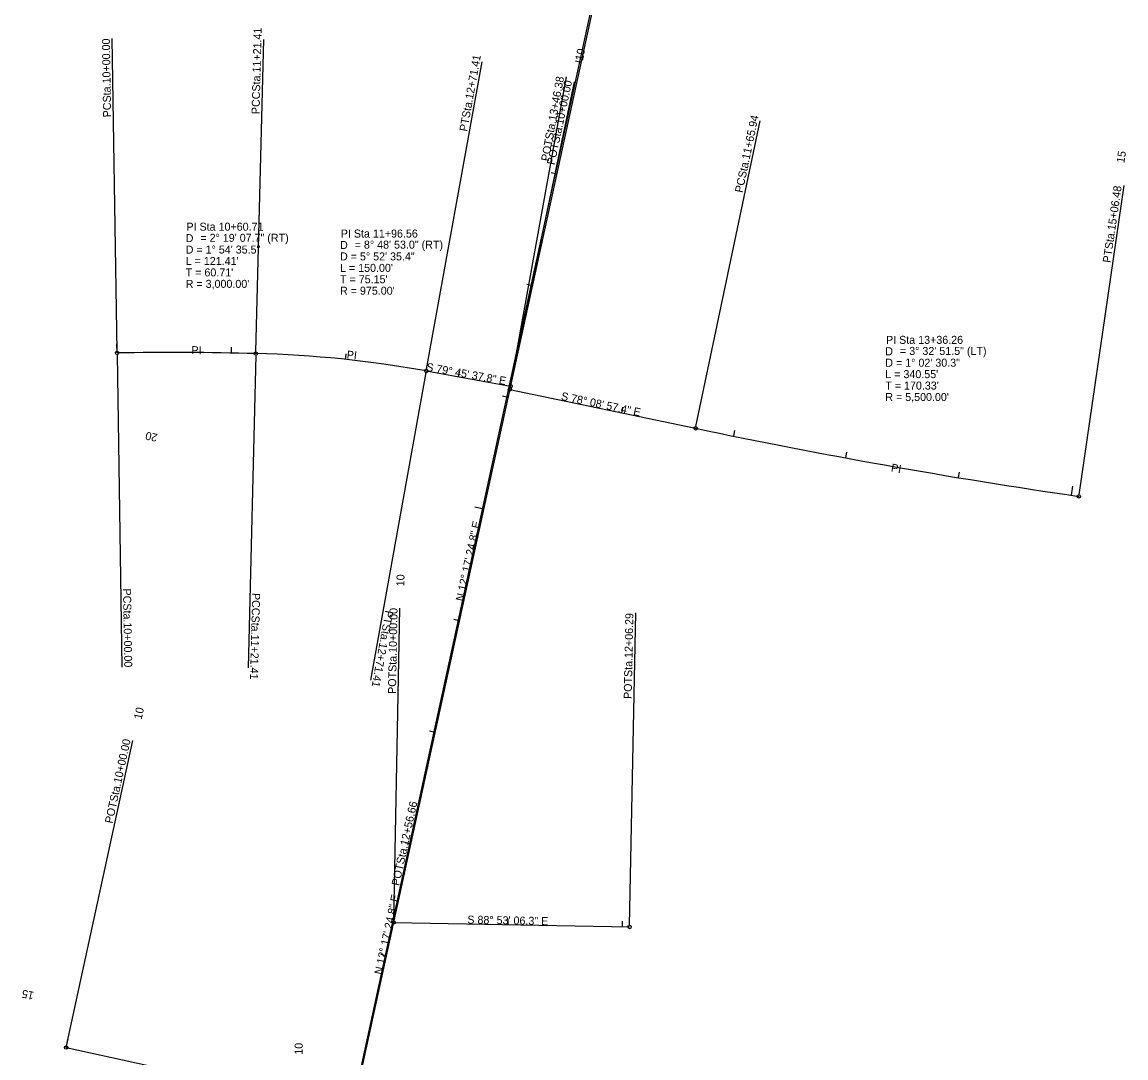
# Model space of a CAD drawing. Extents: x 1615740 to 1617154, y 899624 to 904812.
# Drawn here: x 1615997 to 1616963, y 900122 to 901029 of the extents above; entities that cross this region are included whole.
import ezdxf

# ---------------------------------------------------------------- set-up
doc = ezdxf.new("R2010")
doc.units = 0
for name, color, linetype in [('Default', 7, 'Continuous'), ('Exist Plan Preparation Drainage Flow Arrows', 7, 'Continuous'), ('Exist Plan Preparation Drainage Notes Label', 7, 'Continuous'), ('Exist Structure Minor Pipes CMP 15 Inch Text', 7, 'Continuous'), ('Exist Structure Minor Pipes CMP 24 Inch Text', 7, 'Continuous'), ('Exist Structure Minor Pipes RCP 12 Inch Text', 7, 'Continuous'), ('Exist Structure Minor Pipes RCP 24 Inch Text', 7, 'Continuous'), ('Prop Plan Preparation Sag', 7, 'Continuous'), ('Scratch_Level_7', 7, 'Continuous')]:
    doc.layers.add(name, color=color, linetype=linetype)

msp = doc.modelspace()

# ---------------------------------------------------------------- linework, layer by layer
at = {"layer": 'Default'}
for p, q in [((1616230.15, 899820.83), (1616641.95, 901715.87)), ((1616187.68, 899625.39), (1616607.18, 901555.86)), ((1616187.68, 899625.39), (1616542.07, 901256.25)), ((1616187.68, 899625.39), (1616542.07, 901256.25)), ((1616187.68, 899625.39), (1616542.07, 901256.25)), ((1616187.68, 899625.39), (1616542.07, 901256.25))]:
    msp.add_line(p, q, dxfattribs=at)
at = {"layer": 'Exist Plan Preparation Drainage Flow Arrows'}
for p, q in [((1616080.31, 900739.07), (1616080.19, 900747.07)), ((1616080.31, 900739.07), (1616080.19, 900747.07)), ((1616080.31, 900739.07), (1616080.19, 900747.07)), ((1616080.31, 900739.07), (1616080.19, 900747.07)), ((1616423.96, 900707.19), (1616425.6, 900715.02)), ((1616423.96, 900707.19), (1616425.6, 900715.02)), ((1616423.96, 900707.19), (1616425.6, 900715.02)), ((1616423.96, 900707.19), (1616425.6, 900715.02)), ((1616915.19, 900614.47), (1616916.35, 900622.39)), ((1616915.19, 900614.47), (1616916.35, 900622.39)), ((1616915.19, 900614.47), (1616916.35, 900622.39)), ((1616915.19, 900614.47), (1616916.35, 900622.39)), ((1616401.12, 900602.34), (1616393.3, 900604.05)), ((1616401.12, 900602.34), (1616393.3, 900604.05)), ((1616401.12, 900602.34), (1616393.3, 900604.05)), ((1616401.12, 900602.34), (1616393.3, 900604.05)), ((1616322.36, 900240.83), (1616322.52, 900248.83)), ((1616322.36, 900240.83), (1616322.52, 900248.83)), ((1616322.36, 900240.83), (1616322.52, 900248.83)), ((1616322.36, 900240.83), (1616322.52, 900248.83)), ((1616035.81, 900131.25), (1616037.51, 900139.06)), ((1616035.81, 900131.25), (1616037.51, 900139.06))]:
    msp.add_line(p, q, dxfattribs=at)
at = {"layer": 'Exist Plan Preparation Drainage Notes Label'}
for p, q in [((1616486.27, 900993.18), (1616481.38, 900994.24)), ((1616486.27, 900993.18), (1616481.38, 900994.24)), ((1616486.27, 900993.18), (1616481.38, 900994.24)), ((1616486.27, 900993.18), (1616481.38, 900994.24)), ((1616464.98, 900895.47), (1616460.09, 900896.53)), ((1616464.98, 900895.47), (1616460.09, 900896.53)), ((1616464.98, 900895.47), (1616460.09, 900896.53)), ((1616464.98, 900895.47), (1616460.09, 900896.53)), ((1616443.69, 900797.76), (1616438.81, 900798.82)), ((1616443.69, 900797.76), (1616438.81, 900798.82)), ((1616443.69, 900797.76), (1616438.81, 900798.82)), ((1616443.69, 900797.76), (1616438.81, 900798.82)), ((1616180.31, 900738.96), (1616180.4, 900743.96)), ((1616180.31, 900738.96), (1616180.4, 900743.96)), ((1616180.31, 900738.96), (1616180.4, 900743.96)), ((1616180.31, 900738.96), (1616180.4, 900743.96)), ((1616280.12, 900733.39), (1616280.64, 900738.36)), ((1616280.12, 900733.39), (1616280.64, 900738.36)), ((1616280.12, 900733.39), (1616280.64, 900738.36)), ((1616280.12, 900733.39), (1616280.64, 900738.36)), ((1616378.93, 900718.19), (1616379.82, 900723.12)), ((1616378.93, 900718.19), (1616379.82, 900723.12)), ((1616378.93, 900718.19), (1616379.82, 900723.12)), ((1616378.93, 900718.19), (1616379.82, 900723.12)), ((1616422.41, 900700.05), (1616417.52, 900701.11)), ((1616422.41, 900700.05), (1616417.52, 900701.11)), ((1616422.41, 900700.05), (1616417.52, 900701.11)), ((1616422.41, 900700.05), (1616417.52, 900701.11)), ((1616521.83, 900686.65), (1616522.86, 900691.54)), ((1616521.83, 900686.65), (1616522.86, 900691.54)), ((1616521.83, 900686.65), (1616522.86, 900691.54)), ((1616521.83, 900686.65), (1616522.86, 900691.54)), ((1616619.72, 900666.22), (1616620.72, 900671.12)), ((1616619.72, 900666.22), (1616620.72, 900671.12)), ((1616619.72, 900666.22), (1616620.72, 900671.12)), ((1616619.72, 900666.22), (1616620.72, 900671.12)), ((1616717.89, 900647.18), (1616718.8, 900652.1)), ((1616717.89, 900647.18), (1616718.8, 900652.1)), ((1616717.89, 900647.18), (1616718.8, 900652.1)), ((1616717.89, 900647.18), (1616718.8, 900652.1)), ((1616816.39, 900629.93), (1616817.21, 900634.86)), ((1616816.39, 900629.93), (1616817.21, 900634.86)), ((1616816.39, 900629.93), (1616817.21, 900634.86)), ((1616816.39, 900629.93), (1616817.21, 900634.86)), ((1616379.83, 900504.63), (1616374.95, 900505.7)), ((1616379.83, 900504.63), (1616374.95, 900505.7)), ((1616379.83, 900504.63), (1616374.95, 900505.7)), ((1616379.83, 900504.63), (1616374.95, 900505.7)), ((1616358.55, 900406.93), (1616353.66, 900407.99)), ((1616358.55, 900406.93), (1616353.66, 900407.99)), ((1616358.55, 900406.93), (1616353.66, 900407.99)), ((1616358.55, 900406.93), (1616353.66, 900407.99)), ((1616337.26, 900309.22), (1616332.38, 900310.28)), ((1616337.26, 900309.22), (1616332.38, 900310.28)), ((1616337.26, 900309.22), (1616332.38, 900310.28)), ((1616337.26, 900309.22), (1616332.38, 900310.28)), ((1616422.34, 900238.88), (1616422.44, 900243.88)), ((1616422.34, 900238.88), (1616422.44, 900243.88)), ((1616422.34, 900238.88), (1616422.44, 900243.88)), ((1616422.34, 900238.88), (1616422.44, 900243.88)), ((1616522.33, 900236.94), (1616522.42, 900241.94)), ((1616522.33, 900236.94), (1616522.42, 900241.94)), ((1616522.33, 900236.94), (1616522.42, 900241.94)), ((1616522.33, 900236.94), (1616522.42, 900241.94)), ((1616315.98, 900211.51), (1616311.09, 900212.57)), ((1616315.98, 900211.51), (1616311.09, 900212.57)), ((1616315.98, 900211.51), (1616311.09, 900212.57)), ((1616315.98, 900211.51), (1616311.09, 900212.57))]:
    msp.add_line(p, q, dxfattribs=at)
at = {"layer": 'Exist Structure Minor Pipes CMP 24 Inch Text'}
for p, q in [((1616188.26, 899625.26), (1616593.64, 901486.05)), ((1616350.79, 900723.28), (1616424.56, 900709.95)), ((1616423.96, 900707.19), (1616586.36, 900673.11)), ((1616322.36, 900240.83), (1616528.62, 900236.81)), ((1616035.81, 900131.25), (1616286.61, 900076.72))]:
    msp.add_line(p, q, dxfattribs=at)
for centre, radius, start, end in [((1616127.12, 897739.43), 3000, 88.57523, 90.89404), ((1616177.48, 899763.81), 975, 79.7605, 88.57523), ((1617715.85, 906055.88), 5500, 258.14927, 261.6969)]:
    msp.add_arc(centre, radius, start, end, dxfattribs=at)
at = {"layer": 'Exist Structure Minor Pipes RCP 12 Inch Text'}
msp.add_line((1616230.15, 899820.83), (1616641.93, 901715.79), dxfattribs=at)
at = {"layer": 'Prop Plan Preparation Sag'}
for p, q in [((1616080.29, 900740.57), (1616076.02, 901014.03)), ((1616201.76, 900740), (1616208.56, 901013.42)), ((1616351.06, 900724.75), (1616399.68, 900993.9)), ((1616424.83, 900711.43), (1616473.45, 900980.57)), ((1616424.83, 900711.43), (1616473.45, 900980.57)), ((1616424.83, 900711.43), (1616473.45, 900980.57)), ((1616424.83, 900711.43), (1616473.45, 900980.57)), ((1616424.27, 900708.65), (1616480.44, 900976.32)), ((1616424.27, 900708.65), (1616480.44, 900976.32)), ((1616424.27, 900708.65), (1616480.44, 900976.32)), ((1616424.27, 900708.65), (1616480.44, 900976.32)), ((1616586.67, 900674.58), (1616642.84, 900942.25)), ((1616586.67, 900674.58), (1616642.84, 900942.25)), ((1616586.67, 900674.58), (1616642.84, 900942.25)), ((1616586.67, 900674.58), (1616642.84, 900942.25)), ((1616921.82, 900615.02), (1616961.31, 900885.65)), ((1616921.82, 900615.02), (1616961.31, 900885.65)), ((1616921.82, 900615.02), (1616961.31, 900885.65)), ((1616921.82, 900615.02), (1616961.31, 900885.65)), ((1616080.34, 900737.57), (1616084.61, 900464.1)), ((1616080.34, 900737.57), (1616084.61, 900464.1)), ((1616080.34, 900737.57), (1616084.61, 900464.1)), ((1616201.68, 900737), (1616194.88, 900463.59)), ((1616201.68, 900737), (1616194.88, 900463.59)), ((1616201.68, 900737), (1616194.88, 900463.59)), ((1616350.53, 900721.8), (1616301.91, 900452.66)), ((1616350.53, 900721.8), (1616301.91, 900452.66)), ((1616350.53, 900721.8), (1616301.91, 900452.66)), ((1616322.39, 900242.33), (1616327.71, 900515.78)), ((1616322.39, 900242.33), (1616327.71, 900515.78)), ((1616322.39, 900242.33), (1616327.71, 900515.78)), ((1616322.39, 900242.33), (1616327.71, 900515.78)), ((1616528.65, 900238.31), (1616533.97, 900511.76)), ((1616528.65, 900238.31), (1616533.97, 900511.76)), ((1616528.65, 900238.31), (1616533.97, 900511.76)), ((1616528.65, 900238.31), (1616533.97, 900511.76)), ((1616036.13, 900132.71), (1616094.23, 900399.97)), ((1616036.13, 900132.71), (1616094.23, 900399.97)), ((1616286.93, 900078.19), (1616345.03, 900345.44)), ((1616286.93, 900078.19), (1616345.03, 900345.44))]:
    msp.add_line(p, q, dxfattribs=at)
for centre in [(1616080.31, 900739.07), (1616080.31, 900739.07), (1616080.31, 900739.07), (1616080.31, 900739.07), (1616201.72, 900738.5), (1616201.72, 900738.5), (1616201.72, 900738.5), (1616201.72, 900738.5), (1616350.79, 900723.28), (1616350.79, 900723.28), (1616350.79, 900723.28), (1616350.79, 900723.28), (1616423.96, 900707.19), (1616423.96, 900707.19), (1616423.96, 900707.19), (1616423.96, 900707.19), (1616424.56, 900709.95), (1616424.56, 900709.95), (1616424.56, 900709.95), (1616424.56, 900709.95), (1616586.36, 900673.11), (1616586.36, 900673.11), (1616586.36, 900673.11), (1616586.36, 900673.11), (1616921.6, 900613.53), (1616921.6, 900613.53), (1616921.6, 900613.53), (1616921.6, 900613.53), (1616322.36, 900240.83), (1616322.36, 900240.83), (1616322.36, 900240.83), (1616322.36, 900240.83), (1616528.62, 900236.81), (1616528.62, 900236.81), (1616528.62, 900236.81), (1616528.62, 900236.81), (1616035.81, 900131.25), (1616035.81, 900131.25)]:
    msp.add_circle(centre, 1.5, dxfattribs=at)

# ---------------------------------------------------------------- texts
at = {"layer": 'Default'}
for rotation, p in [(359.73463, (1616145.34, 900737.99)), (359.73463, (1616145.34, 900737.99)), (354.16786, (1616280.94, 900734.21)), (354.16786, (1616280.94, 900734.21)), (349.92309, (1616756.96, 900635.4)), (349.92309, (1616756.96, 900635.4))]:
    msp.add_text('PI ', height=7, rotation=rotation, dxfattribs=at).set_placement(p)
at = {"layer": 'Exist Structure Minor Pipes CMP 15 Inch Text'}
for s, rotation, p in [('S 79%%d 45\' 37.8" E', 349.7605, (1616350.41, 900723.55)), ('S 79%%d 45\' 37.8" E', 349.7605, (1616350.41, 900723.55)), ('S 78%%d 08\' 57.4" E', 348.14927, (1616468.26, 900698.09)), ('S 78%%d 08\' 57.4" E', 348.14927, (1616468.26, 900698.09)), ('N 12%%d 17\' 24.8" E', 77.70978, (1616383.27, 900521.35)), ('N 12%%d 17\' 24.8" E', 77.70978, (1616383.27, 900521.35)), ('N 12%%d 17\' 24.8" E', 77.70978, (1616383.27, 900521.35)), ('N 12%%d 17\' 24.8" E', 77.70978, (1616383.27, 900521.35)), ('N 12%%d 17\' 24.8" E', 77.70978, (1616312.1, 900194.67)), ('N 12%%d 17\' 24.8" E', 77.70978, (1616312.1, 900194.67)), ('S 88%%d 53\' 06.3" E', 358.88509, (1616386.66, 900239.78)), ('S 88%%d 53\' 06.3" E', 358.88509, (1616386.66, 900239.78))]:
    msp.add_text(s, height=7, rotation=rotation, dxfattribs=at).set_placement(p)
at = {"layer": 'Exist Structure Minor Pipes RCP 24 Inch Text'}
for s, p in [('PI Sta 10+60.71', (1616141, 900846)), ('PI Sta 10+60.71', (1616141, 900846)), ('D', (1616140.33, 900836)), ('D', (1616140.33, 900836)), ('= 2%%d 19\' 07.7" (RT)', (1616153.18, 900836.3)), ('= 2%%d 19\' 07.7" (RT)', (1616153.18, 900836.3)), ('PI Sta 11+96.56', (1616276, 900840)), ('PI Sta 11+96.56', (1616276, 900840)), ('D = 1%%d 54\' 35.5"', (1616140.33, 900826)), ('D = 1%%d 54\' 35.5"', (1616140.33, 900826)), ('D', (1616275.33, 900830)), ('D', (1616275.33, 900830)), ('= 8%%d 48\' 53.0" (RT)', (1616288.18, 900830.3)), ('= 8%%d 48\' 53.0" (RT)', (1616288.18, 900830.3)), ("L = 121.41'", (1616140.33, 900816)), ("L = 121.41'", (1616140.33, 900816)), ('D = 5%%d 52\' 35.4"', (1616275.33, 900820)), ('D = 5%%d 52\' 35.4"', (1616275.33, 900820)), ("L = 150.00'", (1616275.33, 900810)), ("L = 150.00'", (1616275.33, 900810)), ("T = 60.71'", (1616140.33, 900806)), ("T = 60.71'", (1616140.33, 900806)), ("T = 75.15'", (1616275.33, 900800)), ("T = 75.15'", (1616275.33, 900800)), ("R = 3,000.00'", (1616140.33, 900796)), ("R = 3,000.00'", (1616140.33, 900796)), ("R = 975.00'", (1616275.33, 900790)), ("R = 975.00'", (1616275.33, 900790)), ('PI Sta 13+36.26', (1616753, 900747)), ('PI Sta 13+36.26', (1616753, 900747)), ('D', (1616752.33, 900737)), ('D', (1616752.33, 900737)), ('= 3%%d 32\' 51.5" (LT)', (1616765.18, 900737.3)), ('= 3%%d 32\' 51.5" (LT)', (1616765.18, 900737.3)), ('D = 1%%d 02\' 30.3"', (1616752.33, 900727)), ('D = 1%%d 02\' 30.3"', (1616752.33, 900727)), ("L = 340.55'", (1616752.33, 900717)), ("L = 340.55'", (1616752.33, 900717)), ("T = 170.33'", (1616752.33, 900707)), ("T = 170.33'", (1616752.33, 900707)), ("R = 5,500.00'", (1616752.33, 900697)), ("R = 5,500.00'", (1616752.33, 900697))]:
    msp.add_text(s, height=7, dxfattribs=at).set_placement(p)
at = {"layer": 'Prop Plan Preparation Sag'}
for s, rotation, p in [('PCCSta.11+21.41', 88.57523, (1616204.93, 900947.91)), ('PCSta.10+00.00', 90.89404, (1616075.1, 900945.23)), ('PTSta.12+71.41', 79.7605, (1616386.54, 900932.43)), ('POTSta.13+46.38', 79.7605, (1616458.01, 900906.36)), ('POTSta.13+46.38', 79.7605, (1616458.01, 900906.36)), ('POTSta.13+46.38', 79.7605, (1616458.01, 900906.36)), ('POTSta.13+46.38', 79.7605, (1616458.01, 900906.36)), ('POTSta.10+00.00', 78.14927, (1616463.04, 900903.17)), ('POTSta.10+00.00', 78.14927, (1616463.04, 900903.17)), ('POTSta.10+00.00', 78.14927, (1616463.04, 900903.17)), ('POTSta.10+00.00', 78.14927, (1616463.04, 900903.17)), ('PCSta.11+65.94', 78.14927, (1616627.48, 900878.8)), ('PCSta.11+65.94', 78.14927, (1616627.48, 900878.8)), ('PCSta.11+65.94', 78.14927, (1616627.48, 900878.8)), ('PCSta.11+65.94', 78.14927, (1616627.48, 900878.8)), ('PTSta.15+06.48', 81.6969, (1616949.36, 900817.61)), ('PTSta.15+06.48', 81.6969, (1616949.36, 900817.61)), ('PTSta.15+06.48', 81.6969, (1616949.36, 900817.61)), ('PTSta.15+06.48', 81.6969, (1616949.36, 900817.61)), ('PCSta.10+00.00', 270.89404, (1616085.53, 900532.9)), ('PCSta.10+00.00', 270.89404, (1616085.53, 900532.9)), ('PCSta.10+00.00', 270.89404, (1616085.53, 900532.9)), ('PCCSta.11+21.41', 268.57523, (1616198.51, 900529.1)), ('PCCSta.11+21.41', 268.57523, (1616198.51, 900529.1)), ('PCCSta.11+21.41', 268.57523, (1616198.51, 900529.1)), ('POTSta.10+00.00', 88.88509, (1616324.25, 900440.66)), ('POTSta.10+00.00', 88.88509, (1616324.25, 900440.66)), ('POTSta.10+00.00', 88.88509, (1616324.25, 900440.66)), ('POTSta.10+00.00', 88.88509, (1616324.25, 900440.66)), ('PTSta.12+71.41', 259.7605, (1616315.05, 900514.12)), ('PTSta.12+71.41', 259.7605, (1616315.05, 900514.12)), ('PTSta.12+71.41', 259.7605, (1616315.05, 900514.12)), ('POTSta.12+06.29', 88.88509, (1616530.5, 900436.21)), ('POTSta.12+06.29', 88.88509, (1616530.5, 900436.21)), ('POTSta.12+06.29', 88.88509, (1616530.5, 900436.21)), ('POTSta.12+06.29', 88.88509, (1616530.5, 900436.21)), ('POTSta.10+00.00', 77.73429, (1616076.31, 900326.94)), ('POTSta.10+00.00', 77.73429, (1616076.31, 900326.94)), ('POTSta.12+56.66', 77.73429, (1616327.11, 900272.41)), ('POTSta.12+56.66', 77.73429, (1616327.11, 900272.41))]:
    msp.add_text(s, height=7, rotation=rotation, dxfattribs=at).set_placement(p)
at = {"layer": 'Scratch_Level_7'}
for s, rotation, p in [('10', 78.14927, (1616487.79, 900994.34)), ('10', 78.14927, (1616487.79, 900994.34)), ('10', 78.14927, (1616487.79, 900994.34)), ('10', 78.14927, (1616487.79, 900994.34)), ('15', 81.62937, (1616961.46, 900904.89)), ('15', 81.62937, (1616961.46, 900904.89)), ('15', 81.62937, (1616961.46, 900904.89)), ('15', 81.62937, (1616961.46, 900904.89)), ('20', 167.70978, (1616116.19, 900668)), ('20', 167.70978, (1616116.19, 900668)), ('20', 167.70978, (1616116.19, 900668)), ('20', 167.70978, (1616116.19, 900668)), ('10', 88.88509, (1616331.59, 900534.85)), ('10', 88.88509, (1616331.59, 900534.85)), ('10', 88.88509, (1616331.59, 900534.85)), ('10', 88.88509, (1616331.59, 900534.85)), ('10', 77.73429, (1616101.72, 900417.93)), ('10', 77.73429, (1616101.72, 900417.93)), ('15', 167.70978, (1616008.11, 900179.82)), ('15', 167.70978, (1616008.11, 900179.82)), ('15', 167.70978, (1616008.11, 900179.82)), ('15', 167.70978, (1616008.11, 900179.82)), ('10', 88.83708, (1616242.54, 900124.96)), ('10', 88.83708, (1616242.54, 900124.96)), ('10', 88.83708, (1616242.54, 900124.96)), ('10', 88.83708, (1616242.54, 900124.96))]:
    msp.add_text(s, height=7, rotation=rotation, dxfattribs=at).set_placement(p)

doc.saveas('drawing.dxf')
